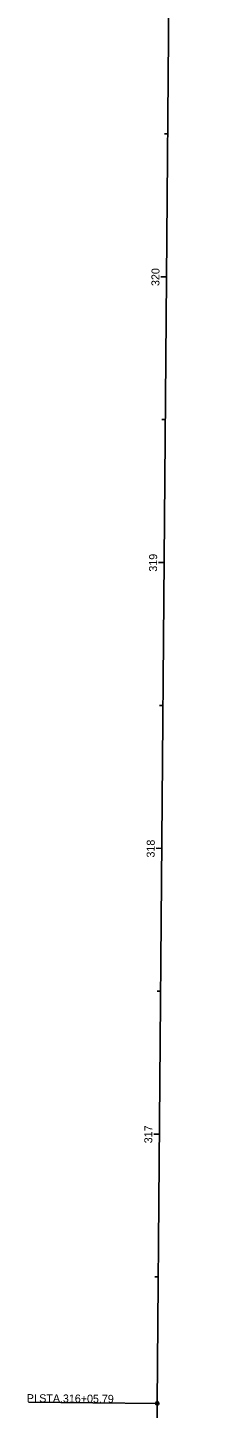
# Model space of a CAD drawing. Extents: x 1504466 to 1504712, y 322450 to 329957.
# Drawn here: x 1504553.1 to 1504614.2, y 328058.1 to 328541.3 of the extents above; entities that cross this region are included whole.
import ezdxf

# ---------------------------------------------------------------- set-up
doc = ezdxf.new("R2010")
doc.units = 0
for name, color, linetype in [('GE_X_Alignment', 7, 'Continuous'), ('GE_X_Alignment_100_Cardinal_Points', 7, 'Continuous'), ('GE_X_Alignment_100_Stations', 7, 'Continuous'), ('GE_X_Alignment_500_Cardinal_Points', 7, 'Continuous'), ('GE_X_Alignment_500_Stations', 7, 'Continuous')]:
    doc.layers.add(name, color=color, linetype=linetype)

msp = doc.modelspace()

# ---------------------------------------------------------------- linework, layer by layer
at = {"layer": 'GE_X_Alignment'}
for p, q in [((1504598.44, 328059.91), (1504614.24, 329953.98)), ((1504576.71, 325454.21), (1504598.44, 328059.91))]:
    msp.add_line(p, q, dxfattribs=at)
at = {"layer": 'GE_X_Alignment_100_Cardinal_Points'}
msp.add_line((1504598.44, 328059.91), (1504553.44, 328060.28), dxfattribs=at)
msp.add_circle((1504598.44, 328059.91), 0.6, dxfattribs=at)
at = {"layer": 'GE_X_Alignment_100_Stations'}
for p, q in [((1504602.15, 328504.1), (1504600.95, 328504.11)), ((1504601.73, 328454.1), (1504599.73, 328454.12)), ((1504601.31, 328404.11), (1504600.11, 328404.12)), ((1504600.9, 328354.11), (1504598.9, 328354.12)), ((1504600.48, 328304.11), (1504599.28, 328304.12)), ((1504600.06, 328254.11), (1504598.06, 328254.13)), ((1504599.64, 328204.11), (1504598.44, 328204.12)), ((1504599.23, 328154.11), (1504597.23, 328154.13)), ((1504598.81, 328104.12), (1504597.61, 328104.13))]:
    msp.add_line(p, q, dxfattribs=at)
at = {"layer": 'GE_X_Alignment_500_Cardinal_Points'}
msp.add_line((1504598.44, 328059.91), (1504553.44, 328060.28), dxfattribs=at)
msp.add_circle((1504598.44, 328059.91), 0.6, dxfattribs=at)
at = {"layer": 'GE_X_Alignment_500_Stations'}
for p, q in [((1504601.73, 328454.1), (1504599.73, 328454.12)), ((1504600.9, 328354.11), (1504599.7, 328354.12)), ((1504600.06, 328254.11), (1504598.86, 328254.12)), ((1504599.23, 328154.11), (1504598.03, 328154.12))]:
    msp.add_line(p, q, dxfattribs=at)

# ---------------------------------------------------------------- texts
at = {"layer": 'GE_X_Alignment_100_Cardinal_Points'}
for s, p in [('PI', (1504552.79, 328060.33)), (' STA. ', (1504556.11, 328060.3)), ('316+05.79', (1504565.43, 328060.22))]:
    msp.add_text(s, height=2.8, rotation=359.5221, dxfattribs=at).set_placement(p)
at = {"layer": 'GE_X_Alignment_100_Stations'}
for s, p in [('320', (1504599.2, 328450.86)), ('319', (1504598.37, 328350.9)), ('318', (1504597.53, 328250.88)), ('317', (1504596.7, 328150.89))]:
    msp.add_text(s, height=2.8, rotation=89.5221, dxfattribs=at).set_placement(p)
at = {"layer": 'GE_X_Alignment_500_Cardinal_Points'}
for s, p in [('PI', (1504552.79, 328060.33)), (' STA. ', (1504556.11, 328060.3)), ('316+05.79', (1504565.43, 328060.22))]:
    msp.add_text(s, height=2.8, rotation=359.5221, dxfattribs=at).set_placement(p)
at = {"layer": 'GE_X_Alignment_500_Stations'}
msp.add_text('320', height=2.8, rotation=89.5221, dxfattribs=at).set_placement((1504599.2, 328450.86))

doc.saveas('drawing.dxf')
